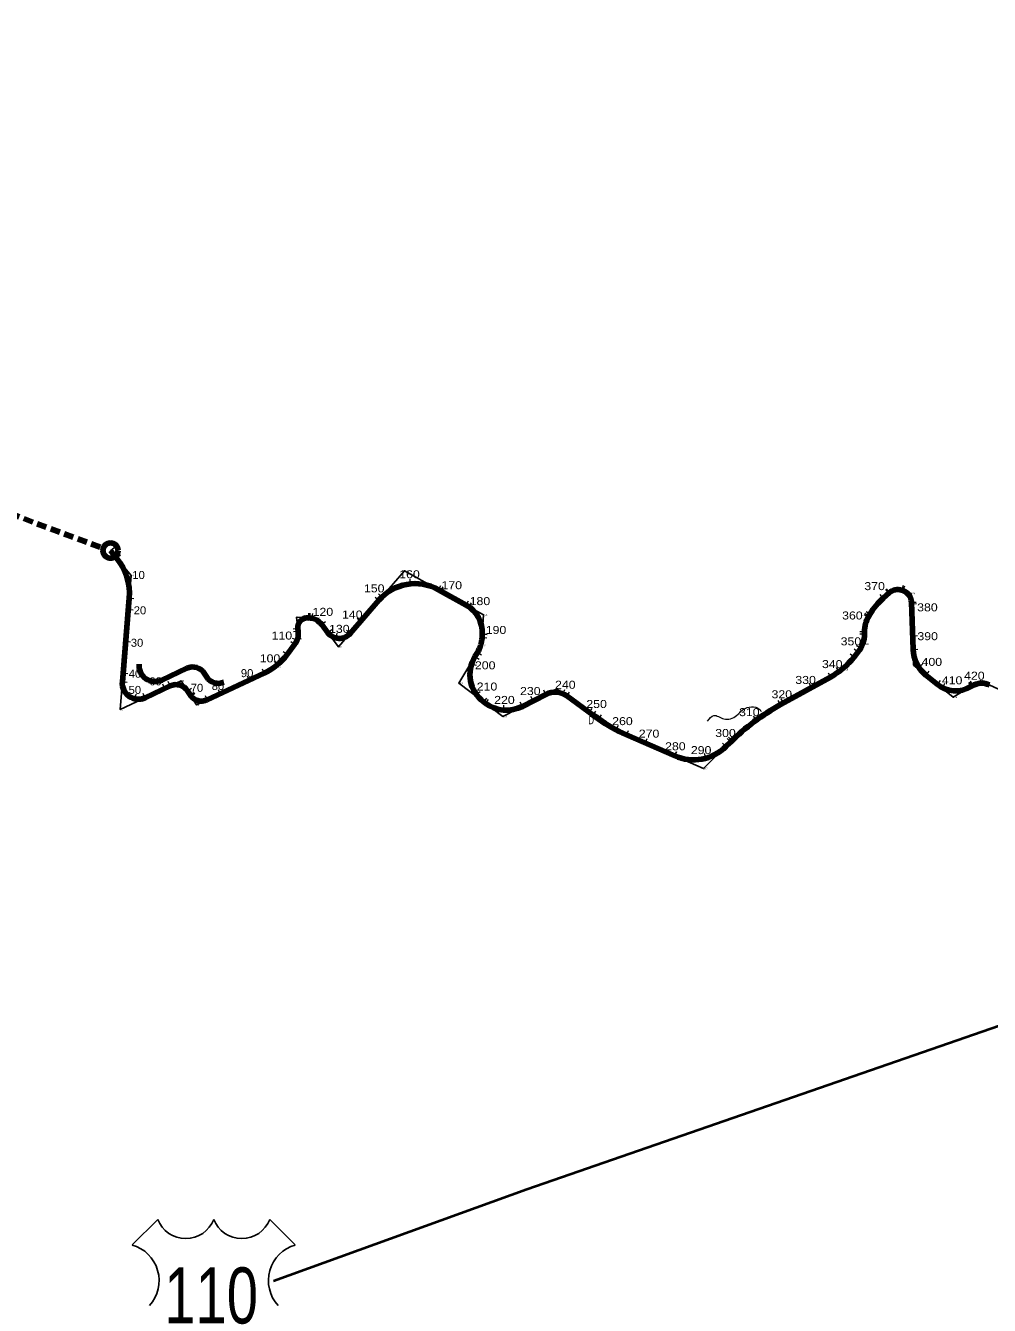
# Model space of a CAD drawing. Extents: x 553962 to 842807, y 8883888 to 9032388.
# Drawn here: x 591570 to 597590, y 8961821 to 8969814 of the extents above; entities that cross this region are included whole.
import ezdxf
from ezdxf.enums import TextEntityAlignment as Align

# ---------------------------------------------------------------- set-up
doc = ezdxf.new("R2010")
doc.units = 0
doc.header["$LTSCALE"] = 20
doc.linetypes.add('MEDIUM_DASHED', pattern=[4.5, 3, -1.5])
for name, color, linetype, lineweight in [('12', 7, 'Continuous', 25), ('14', 7, 'Continuous', 13), ('15', 7, 'Continuous', 90), ('26', 7, 'Continuous', 13), ('27', 7, 'Continuous', 13), ('48', 7, 'Continuous', 25), ('60', 7, 'Continuous', 25), ('9', 7, 'Continuous', 90)]:
    doc.layers.add(name, color=color, linetype=linetype, lineweight=lineweight)
doc.layers.add('13', color=7, linetype='Continuous')
doc.layers.add('61', color=7, linetype='Continuous')

msp = doc.modelspace()

# ---------------------------------------------------------------- linework, layer by layer
at = {"layer": '12', "lineweight": 40}
msp.add_lwpolyline([(593118.32, 8961975.46), (594700.75, 8962547.46), (600985.52, 8964722.42), (602091.61, 8965119.89), (602697.14, 8965318.89), (609861.02, 8967928.67)], dxfattribs=at)
at = {"layer": '14'}
for p, q in [((592100.12, 8966535.41), (592123.3, 8966554.46)), ((592138.38, 8966488.86), (592161.56, 8966507.91)), ((592203.51, 8966366.27), (592232.27, 8966374.81)), ((593969.03, 8966357.29), (593972.16, 8966327.46)), ((593753.69, 8966244.76), (593776.4, 8966225.15)), ((593773.46, 8966265.73), (593794.37, 8966244.22)), ((594149.38, 8966291.21), (594163.97, 8966317.42)), ((594163.58, 8966283.3), (594178.17, 8966309.52)), ((596927.13, 8966237.96), (596907.15, 8966260.34)), ((596927.13, 8966237.96), (596966.92, 8966273.47)), ((596962.82, 8966269.81), (596942.85, 8966292.2)), ((596966.92, 8966273.47), (596946.94, 8966295.85)), ((597051.8, 8966316.53), (597041.82, 8966288.24)), ((597041.82, 8966288.24), (597050.5, 8966285.18)), ((597060.49, 8966313.47), (597050.5, 8966285.18)), ((592211.1, 8966167.94), (592241, 8966165.49)), ((592216.84, 8966238.09), (592246.74, 8966235.64)), ((594322.59, 8966194.79), (594337.18, 8966221)), ((594337.9, 8966185.32), (594354.85, 8966210.07)), ((597103.83, 8966212.42), (597133.81, 8966213.43)), ((597103.83, 8966212.42), (597113.72, 8965917.79)), ((597104.14, 8966203.06), (597134.13, 8966204.06)), ((593336.38, 8966144.88), (593334.29, 8966114.96)), ((593345.48, 8966144.25), (593343.4, 8966114.32)), ((593361.44, 8966142.17), (593355.81, 8966112.71)), ((593443.72, 8966091.06), (593419.8, 8966072.95)), ((593640.11, 8966113.21), (593662.81, 8966093.61)), ((596833.3, 8966119.11), (596807.01, 8966133.57)), ((596837.45, 8966126.36), (596811.79, 8966141.89)), ((596837.45, 8966126.36), (596811.79, 8966141.89)), ((596819.93, 8966155.35), (596845.6, 8966139.81)), ((596837.45, 8966126.36), (596845.6, 8966139.81)), ((593270.53, 8966048.04), (593240.74, 8966044.51)), ((593272.56, 8966030.89), (593242.77, 8966027.36)), ((593481.76, 8966040.82), (593457.84, 8966022.71)), ((593514.35, 8966019), (593506.73, 8965989.99)), ((593575.01, 8966037.82), (593597.72, 8966018.22)), ((594452.31, 8966010.45), (594422.37, 8966012.31)), ((594422.45, 8966013.66), (594452.4, 8966012.01)), ((596810, 8966027.98), (596780, 8966027.98)), ((596780, 8966016.13), (596810, 8966016.13)), ((596810, 8966016.13), (596810, 8966027.98)), ((597110.85, 8966003.17), (597140.84, 8966004.18)), ((592194.8, 8965968.6), (592224.7, 8965966.16)), ((593250.17, 8965948.11), (593226.22, 8965966.17)), ((593265.77, 8965976.28), (593237.75, 8965987)), ((594451.01, 8965989.47), (594421.07, 8965991.33)), ((596787.06, 8965926.93), (596760.74, 8965941.32)), ((593122.28, 8965844.29), (593141.37, 8965821.15)), ((593202.87, 8965885.4), (593178.92, 8965903.46)), ((594376.43, 8965873.69), (594402.06, 8965858.1)), ((594392.31, 8965899.78), (594417.93, 8965884.18)), ((596744.69, 8965869.75), (596721.31, 8965888.55)), ((596744.69, 8965869.75), (596769.19, 8965900.23)), ((596769.19, 8965900.23), (596745.81, 8965919.03)), ((597113.72, 8965917.79), (597143.7, 8965918.8)), ((592178.5, 8965769.27), (592208.4, 8965766.82)), ((593047.74, 8965797.18), (593060.45, 8965770)), ((594355.56, 8965828.18), (594384.1, 8965818.94)), ((596582.31, 8965771.63), (596596.82, 8965745.37)), ((596652.08, 8965780.85), (596634.22, 8965804.96)), ((597147.19, 8965809.63), (597172.54, 8965825.67)), ((597211.83, 8965781.51), (597192.89, 8965758.24)), ((592174.07, 8965715.07), (592203.97, 8965712.63)), ((592439.77, 8965674.44), (592427.01, 8965701.6)), ((592473.48, 8965690.28), (592460.72, 8965717.44)), ((592953.52, 8965753.12), (592966.23, 8965725.94)), ((596285.55, 8965573.36), (596596.82, 8965745.37)), ((596479.29, 8965680.42), (596464.78, 8965706.68)), ((597192.89, 8965758.24), (597263.15, 8965701.07)), ((597282.09, 8965724.34), (597263.15, 8965701.07)), ((597310.43, 8965706.01), (597296.98, 8965679.19)), ((597459.9, 8965711.78), (597475.38, 8965686.09)), ((597467.18, 8965716.17), (597482.66, 8965690.47)), ((597487.18, 8965693.05), (597472.73, 8965719.34)), ((597475.3, 8965686.04), (597482.66, 8965690.47)), ((592254.25, 8965608.84), (592260.09, 8965638.26)), ((592316.26, 8965616.41), (592303.5, 8965643.57)), ((592581.21, 8965659.16), (592606.48, 8965675.34)), ((592596.86, 8965634.72), (592622.13, 8965650.89)), ((592603.55, 8965625.65), (592626.46, 8965645.02)), ((592691.75, 8965630.72), (592704.46, 8965603.54)), ((592772.35, 8965668.4), (592785.06, 8965641.23)), ((594384.74, 8965637.53), (594409.21, 8965654.89)), ((594449.1, 8965613.93), (594431.1, 8965589.93)), ((594459.22, 8965606.34), (594441.22, 8965582.34)), ((594740.24, 8965596.59), (594726.61, 8965623.31)), ((594819.94, 8965637.26), (594806.3, 8965663.98)), ((594926.85, 8965640.45), (594938.88, 8965667.93)), ((594949.95, 8965627.26), (594967.51, 8965651.58)), ((596304.24, 8965583.69), (596289.73, 8965609.95)), ((594555.16, 8965569.2), (594552.31, 8965539.33)), ((594673.23, 8965562.38), (594659.59, 8965589.1)), ((595090.48, 8965525.77), (595108.05, 8965550.09)), ((595114.31, 8965508.56), (595131.87, 8965532.88)), ((596285.55, 8965573.36), (596271.04, 8965599.62)), ((595165.33, 8965508.71), (595147.76, 8965484.39)), ((596135, 8965477.42), (596117.29, 8965501.63)), ((595271.55, 8965442.56), (595257.47, 8965416.07)), ((595322.97, 8965384.42), (595334.97, 8965411.91)), ((595961.24, 8965370.27), (595982.11, 8965348.73)), ((595439.58, 8965333.52), (595451.58, 8965361.01)), ((595923.69, 8965333.3), (595944.76, 8965311.95)), ((595951.61, 8965360.86), (595972.69, 8965339.51)), ((595622.87, 8965253.5), (595634.87, 8965281)), ((595625.03, 8965252.56), (595637.03, 8965280.06)), ((595818.39, 8965238.85), (595810.39, 8965267.76))]:
    msp.add_line(p, q, dxfattribs=at)
for centre, radius, start, end in [((597016.86, 8966217.52), 75, 70.55997, 131.75089), ((597023.88, 8966209.74), 80, 1.92196, 70.55996), ((597213.46, 8965917.16), 430, 131.75089, 148.81502), ((597000, 8966027.98), 190, 148.81502, 180), ((596625, 8966016.13), 185, 321.20777, 0), ((596354.98, 8966182.99), 500, 298.92642, 321.20777), ((597328.6, 8965925), 215, 181.92196, 230.8625), ((597379.92, 8965844.56), 185, 230.8625, 301.0622), ((597379.92, 8965844.56), 185, 243.36383, 301.03315), ((597541.99, 8965591.96), 115, 65.09523, 121.0622), ((596977.22, 8964321.76), 1430, 118.92642, 134.09739)]:
    msp.add_arc(centre, radius, start, end, dxfattribs=at)
msp.add_spline([(595830.1, 8965470.36), (595868.38, 8965505.89), (595932.18, 8965484.24), (596010.41, 8965504.78), (596052.02, 8965543.08), (596152.43, 8965545.85), (596165.19, 8965530.86)], degree=3, dxfattribs=at)
at = {"layer": '15', "linetype": 'MEDIUM_DASHED'}
msp.add_line((590039.76, 8967299.35), (592054.89, 8966550.12), dxfattribs=at)
at = {"layer": '15'}
for p, q in [((592100.12, 8966535.41), (592138.38, 8966488.86)), ((594149.38, 8966291.21), (594322.59, 8966194.79)), ((594149.38, 8966291.21), (594322.59, 8966194.79)), ((596927.13, 8966237.96), (596966.92, 8966273.47)), ((597041.82, 8966288.24), (597050.5, 8966285.18)), ((592216.84, 8966238.09), (592174.07, 8965715.07)), ((593597.72, 8966018.22), (593776.4, 8966225.15)), ((593597.72, 8966018.22), (593776.4, 8966225.15)), ((597103.83, 8966212.42), (597113.72, 8965917.79)), ((593334.29, 8966114.96), (593343.4, 8966114.32)), ((593334.29, 8966114.96), (593343.4, 8966114.32)), ((596837.45, 8966126.36), (596845.6, 8966139.81)), ((593272.56, 8966030.89), (593270.53, 8966048.04)), ((593272.56, 8966030.89), (593270.53, 8966048.04)), ((593419.8, 8966072.95), (593457.84, 8966022.71)), ((593419.8, 8966072.95), (593457.84, 8966022.71)), ((594422.37, 8966012.31), (594421.07, 8965991.33)), ((594422.37, 8966012.31), (594421.07, 8965991.33)), ((596810, 8966016.13), (596810, 8966027.98)), ((593202.87, 8965885.4), (593250.17, 8965948.11)), ((593202.87, 8965885.4), (593250.17, 8965948.11)), ((594392.31, 8965899.78), (594376.43, 8965873.69)), ((594392.31, 8965899.78), (594376.43, 8965873.69)), ((596744.69, 8965869.75), (596769.19, 8965900.23)), ((592420.47, 8965726.85), (592577.69, 8965800.71)), ((592685.42, 8965769.6), (592701.07, 8965745.16)), ((592704.46, 8965603.54), (593060.45, 8965770)), ((592316.26, 8965616.41), (592473.48, 8965690.28)), ((596285.55, 8965573.36), (596596.82, 8965745.37)), ((597192.89, 8965758.24), (597263.16, 8965701.06)), ((597475.3, 8965686.04), (597482.66, 8965690.47)), ((592581.21, 8965659.16), (592596.86, 8965634.72)), ((594673.23, 8965562.38), (594819.94, 8965637.26)), ((594673.23, 8965562.38), (594819.94, 8965637.26)), ((594949.95, 8965627.26), (595114.31, 8965508.56)), ((594949.95, 8965627.26), (595114.31, 8965508.56)), ((594431.1, 8965589.93), (594441.22, 8965582.34)), ((594431.1, 8965589.93), (594441.22, 8965582.34)), ((595114.31, 8965508.55), (595147.76, 8965484.39)), ((595114.31, 8965508.55), (595147.76, 8965484.39)), ((595322.97, 8965384.42), (595625.03, 8965252.56)), ((595322.97, 8965384.42), (595625.03, 8965252.56)), ((595944.76, 8965311.95), (595972.69, 8965339.51)), ((595944.76, 8965311.95), (595972.69, 8965339.51))]:
    msp.add_line(p, q, dxfattribs=at)
msp.add_circle((592100.12, 8966535.41), 47.56, dxfattribs=at)
for centre, radius, start, end in [((591868, 8966266.61), 350, 355.32527, 39.41953), ((594003.46, 8966029.09), 300, 60.89618, 139.19118), ((594003.46, 8966029.09), 300, 60.89618, 139.19118), ((597016.86, 8966217.52), 75, 70.55997, 131.75089), ((597023.88, 8966209.74), 80, 1.92196, 70.55996), ((594227.75, 8966024.41), 195, 356.44215, 60.89618), ((594227.75, 8966024.41), 195, 356.44215, 60.89618), ((597213.46, 8965917.16), 430, 131.75089, 148.81502), ((593330.11, 8966055.1), 60, 86.00909, 186.75908), ((593330.11, 8966055.1), 60, 86.00909, 186.75908), ((593336.09, 8966009.58), 105, 37.12798, 86.00909), ((593336.09, 8966009.58), 105, 37.12798, 86.00909), ((597000, 8966027.98), 190, 148.81502, 180), ((593158.36, 8966017.36), 115, 322.97327, 6.75908), ((593158.36, 8966017.36), 115, 322.97327, 6.75908), ((593529.6, 8966077.04), 90, 217.12799, 319.19119), ((593529.6, 8966077.04), 90, 217.12799, 319.19119), ((596625, 8966016.13), 185, 321.20777, 0), ((594221.45, 8966003.74), 200, 328.67904, 356.44215), ((594221.45, 8966003.74), 200, 328.67904, 356.44215), ((592899.5, 8966114.23), 380, 295.06001, 322.97327), ((592899.5, 8966114.23), 380, 295.06001, 322.97327), ((594560.1, 8965761.93), 215, 148.67904, 233.1301), ((594560.1, 8965761.93), 215, 148.67904, 233.1301), ((596354.98, 8966182.99), 500, 298.92642, 321.20777), ((597328.6, 8965925), 215, 181.92196, 230.8625), ((592377.95, 8965817.36), 100, 175.32527, 295.1649), ((592613.83, 8965723.78), 85, 32.61924, 115.1649), ((592273.74, 8965706.92), 100, 175.32527, 295.1649), ((592509.62, 8965613.34), 85, 32.61924, 115.1649), ((592772.66, 8965790.97), 85, 212.61924, 295.06002), ((597379.92, 8965844.56), 185, 230.86502, 301.03315), ((597541.99, 8965591.96), 115, 65.09523, 121.0622), ((592668.45, 8965680.54), 85, 212.61924, 295.06002), ((594876.76, 8965525.93), 125, 54.16336, 117.03912), ((594876.76, 8965525.93), 125, 54.16336, 117.03912), ((594573.22, 8965758.34), 220, 233.1301, 297.03912), ((594573.22, 8965758.34), 220, 233.1301, 297.03912), ((596977.22, 8964321.76), 1430, 118.92642, 134.62552), ((595701.03, 8966250.5), 945, 234.16361, 246.41769), ((595701.03, 8966250.5), 945, 234.16361, 246.41769), ((595741.05, 8965518.34), 290, 246.41768, 314.62552), ((595741.05, 8965518.34), 290, 246.41768, 314.62552)]:
    msp.add_arc(centre, radius, start, end, dxfattribs=at)
at = {"layer": '26'}
for p, q in [((592100.12, 8966535.41), (592138.38, 8966488.86)), ((594149.38, 8966291.21), (594322.59, 8966194.79)), ((596927.13, 8966237.96), (596966.92, 8966273.47)), ((597041.82, 8966288.24), (597050.5, 8966285.18)), ((592216.84, 8966238.09), (592174.07, 8965715.07)), ((593597.72, 8966018.22), (593776.4, 8966225.15)), ((597103.83, 8966212.42), (597113.72, 8965917.79)), ((593334.29, 8966114.96), (593343.4, 8966114.32)), ((596837.45, 8966126.36), (596845.6, 8966139.81)), ((593272.56, 8966030.89), (593270.53, 8966048.04)), ((593419.8, 8966072.95), (593457.84, 8966022.71)), ((594422.37, 8966012.31), (594421.07, 8965991.33)), ((596810, 8966016.13), (596810, 8966027.98)), ((593202.87, 8965885.4), (593250.17, 8965948.11)), ((594392.31, 8965899.78), (594376.43, 8965873.69)), ((596744.69, 8965869.75), (596769.19, 8965900.23)), ((592704.46, 8965603.54), (593060.45, 8965770)), ((592316.26, 8965616.41), (592473.48, 8965690.28)), ((596285.55, 8965573.36), (596596.82, 8965745.37)), ((597192.89, 8965758.24), (597263.16, 8965701.06)), ((597475.3, 8965686.04), (597482.66, 8965690.47)), ((592581.21, 8965659.16), (592596.86, 8965634.72)), ((594673.23, 8965562.38), (594819.94, 8965637.26)), ((594431.1, 8965589.93), (594441.22, 8965582.34)), ((595322.97, 8965384.42), (595625.03, 8965252.56)), ((595944.76, 8965311.95), (595972.69, 8965339.51))]:
    msp.add_line(p, q, dxfattribs=at)
msp.add_lwpolyline([(594949.95, 8965627.26), (595114.31, 8965508.56), (595147.76, 8965484.39)], dxfattribs=at)
for centre, radius, start, end in [((591868, 8966266.61), 350, 355.32527, 39.41953), ((594003.46, 8966029.09), 300, 60.89618, 139.19118), ((597016.86, 8966217.52), 75, 70.55997, 131.75089), ((597023.88, 8966209.74), 80, 1.92196, 70.55996), ((594227.75, 8966024.41), 195, 356.44215, 60.89618), ((597213.46, 8965917.16), 430, 131.75089, 148.81502), ((593330.11, 8966055.1), 60, 86.00909, 186.75908), ((593336.09, 8966009.58), 105, 37.12798, 86.00909), ((597000, 8966027.98), 190, 148.81502, 180), ((593158.36, 8966017.36), 115, 322.97327, 6.75908), ((593529.6, 8966077.04), 90, 217.12799, 319.19119), ((596625, 8966016.13), 185, 321.20777, 0), ((594221.45, 8966003.74), 200, 328.67904, 356.44215), ((592899.5, 8966114.23), 380, 295.06001, 322.97327), ((594560.1, 8965761.93), 215, 148.67904, 233.1301), ((596354.98, 8966182.99), 500, 298.92642, 321.20777), ((597328.6, 8965925), 215, 181.92196, 230.8625), ((592273.74, 8965706.92), 100, 175.32527, 295.1649), ((592509.62, 8965613.34), 85, 32.61924, 115.1649), ((597379.92, 8965844.56), 185, 230.86502, 301.03315), ((597541.99, 8965591.96), 115, 65.09523, 121.0622), ((592668.45, 8965680.54), 85, 212.61924, 295.06002), ((594876.76, 8965525.93), 125, 54.16336, 117.03912), ((594573.22, 8965758.34), 220, 233.1301, 297.03912), ((596977.22, 8964321.76), 1430, 118.92642, 134.62552), ((595701.03, 8966250.5), 945, 234.16361, 246.41769), ((595741.05, 8965518.34), 290, 246.41768, 314.62552)]:
    msp.add_arc(centre, radius, start, end, dxfattribs=at)
at = {"layer": '27'}
for p, q in [((592100.12, 8966535.41), (592138.38, 8966488.86)), ((594149.38, 8966291.21), (594322.59, 8966194.79)), ((596927.13, 8966237.96), (596966.92, 8966273.47)), ((597041.82, 8966288.24), (597050.5, 8966285.18)), ((592216.84, 8966238.09), (592174.07, 8965715.07)), ((593597.72, 8966018.22), (593776.4, 8966225.15)), ((597103.83, 8966212.42), (597113.72, 8965917.79)), ((593334.29, 8966114.96), (593343.4, 8966114.32)), ((596837.45, 8966126.36), (596845.6, 8966139.81)), ((593272.56, 8966030.89), (593270.53, 8966048.04)), ((593419.8, 8966072.95), (593457.84, 8966022.71)), ((594422.37, 8966012.31), (594421.07, 8965991.33)), ((596810, 8966016.13), (596810, 8966027.98)), ((593202.87, 8965885.4), (593250.17, 8965948.11)), ((594392.31, 8965899.78), (594376.43, 8965873.69)), ((596744.69, 8965869.75), (596769.19, 8965900.23)), ((592704.46, 8965603.54), (593060.45, 8965770)), ((592316.26, 8965616.41), (592473.48, 8965690.28)), ((596285.55, 8965573.36), (596596.82, 8965745.37)), ((597192.89, 8965758.24), (597263.16, 8965701.06)), ((597475.3, 8965686.04), (597482.66, 8965690.47)), ((592581.21, 8965659.16), (592596.86, 8965634.72)), ((594673.23, 8965562.38), (594819.94, 8965637.26)), ((594431.1, 8965589.93), (594441.22, 8965582.34)), ((595322.97, 8965384.42), (595625.03, 8965252.56)), ((595944.76, 8965311.95), (595972.69, 8965339.51))]:
    msp.add_line(p, q, dxfattribs=at)
msp.add_lwpolyline([(594949.95, 8965627.26), (595114.31, 8965508.56), (595147.76, 8965484.39)], dxfattribs=at)
for centre, radius, start, end in [((591868, 8966266.61), 350, 355.32527, 39.41953), ((594003.46, 8966029.09), 300, 60.89618, 139.19118), ((597016.86, 8966217.52), 75, 70.55997, 131.75089), ((597023.88, 8966209.74), 80, 1.92196, 70.55996), ((594227.75, 8966024.41), 195, 356.44215, 60.89618), ((597213.46, 8965917.16), 430, 131.75089, 148.81502), ((593330.11, 8966055.1), 60, 86.00909, 186.75908), ((593336.09, 8966009.58), 105, 37.12798, 86.00909), ((597000, 8966027.98), 190, 148.81502, 180), ((593158.36, 8966017.36), 115, 322.97327, 6.75908), ((593529.6, 8966077.04), 90, 217.12799, 319.19119), ((596625, 8966016.13), 185, 321.20777, 0), ((594221.45, 8966003.74), 200, 328.67904, 356.44215), ((592899.5, 8966114.23), 380, 295.06001, 322.97327), ((594560.1, 8965761.93), 215, 148.67904, 233.1301), ((596354.98, 8966182.99), 500, 298.92642, 321.20777), ((597328.6, 8965925), 215, 181.92196, 230.8625), ((592273.74, 8965706.92), 100, 175.32527, 295.1649), ((592509.62, 8965613.34), 85, 32.61924, 115.1649), ((597379.92, 8965844.56), 185, 230.86502, 301.03315), ((597541.99, 8965591.96), 115, 65.09523, 121.0622), ((592668.45, 8965680.54), 85, 212.61924, 295.06002), ((594876.76, 8965525.93), 125, 54.16336, 117.03912), ((594573.22, 8965758.34), 220, 233.1301, 297.03912), ((596977.22, 8964321.76), 1430, 118.92642, 134.62552), ((595701.03, 8966250.5), 945, 234.16361, 246.41769), ((595741.05, 8965518.34), 290, 246.41768, 314.62552)]:
    msp.add_arc(centre, radius, start, end, dxfattribs=at)
at = {"layer": '48'}
for p, q in [((592235.21, 8962198.42), (592395.14, 8962358.32)), ((593094.46, 8962358.32), (593254.41, 8962198.42))]:
    msp.add_line(p, q, dxfattribs=at)
for centre, radius, start, end in [((592569.98, 8962425.29), 187.21, 200.95927, 339.04073), ((592919.63, 8962425.29), 187.21, 200.95927, 339.04073), ((592173.14, 8961976.56), 230.34, 317.5721, 74.36886), ((593316.47, 8961976.56), 230.34, 105.62774, 222.4279)]:
    msp.add_arc(centre, radius, start, end, dxfattribs=at)
at = {"layer": '60'}
msp.add_lwpolyline([(592100.12, 8966535.41), (592228.39, 8966379.36), (592160, 8965543), (592541, 8965722), (592637, 8965572), (593146, 8965810), (593278, 8965985), (593262, 8966120), (593391, 8966111), (593525, 8965934), (593936, 8966410), (594430, 8966135), (594418, 8965942), (594275, 8965707), (594551, 8965500), (594888, 8965672), (595114.31, 8965508.55), (595230, 8965425), (595805, 8965174), (596113, 8965478), (596683, 8965793), (596810, 8965951), (596810, 8966081), (596879, 8966195), (597000, 8966303), (597102, 8966267), (597117, 8965820), (597364, 8965619), (597535, 8965722), (597647, 8965670)], dxfattribs=at)
at = {"layer": '9'}
msp.add_spline([(592698.54, 8977198.44), (599903.54, 8973292.71), (608459.22, 8968138.19), (612674.79, 8965332.64), (616842.02, 8962096.37), (620004.97, 8958671.19), (621133.98, 8957974.71), (621473.43, 8956805.35), (621586.23, 8956597.47)], degree=3, dxfattribs=at)

# ---------------------------------------------------------------- texts
at = {"layer": '13'}
for s, width, p in [('10', 1.05, (592275.34, 8966358.08)), ('160', 1.15, (593967.89, 8966362.58)), ('150', 1.15, (593747.25, 8966274.56)), ('170', 1.15, (594231.82, 8966294.11)), ('370', 1.15, (596873.14, 8966288.5)), ('180', 1.15, (594407.77, 8966194.91)), ('20', 1.05, (592284.01, 8966137.38)), ('120', 1.15, (593426.78, 8966127.88)), ('380', 1.15, (597203.33, 8966155.96)), ('140', 1.15, (593610.4, 8966111.1)), ('360', 1.15, (596734.56, 8966105.04)), ('110', 1.15, (593170.53, 8965979.79)), ('130', 1.15, (593529.41, 8966021.69)), ('190', 1.15, (594508.31, 8966014.67)), ('390', 1.15, (597204.63, 8965975.76)), ('30', 1.05, (592265.81, 8965934.7)), ('350', 1.15, (596725.27, 8965943.56)), ('100', 1.15, (593096.53, 8965837.29)), ('200', 1.15, (594440.69, 8965793.86)), ('340', 1.15, (596608.66, 8965801.53)), ('400', 1.15, (597230.72, 8965815.14)), ('40', 1.05, (592252.9, 8965741.44)), ('90', 1.05, (592953.4, 8965745.09)), ('420', 1.15, (597496.4, 8965728.95)), ('50', 1.05, (592251.9, 8965640.22)), ('60', 1.05, (592380.86, 8965694.1)), ('70', 1.05, (592640.14, 8965653.52)), ('80', 1.05, (592771.16, 8965664.75)), ('210', 1.15, (594451.95, 8965661.37)), ('240', 1.15, (594941.24, 8965672.63)), ('330', 1.15, (596442.19, 8965702.61)), ('410', 1.15, (597357.41, 8965700.26)), ('220', 1.15, (594560.89, 8965577.74)), ('230', 1.15, (594722.42, 8965633.17)), ('320', 1.15, (596293.46, 8965612.99)), ('250', 1.15, (595136.58, 8965552.35)), ('310', 1.15, (596090.65, 8965501.4)), ('D', 0.65, (595102.96, 8965451.13)), ('260', 1.15, (595298.11, 8965445.23)), ('270', 1.15, (595464.33, 8965367.24)), ('300', 1.15, (595941.92, 8965371.2)), ('280', 1.15, (595628.68, 8965288.31)), ('290', 1.15, (595789.64, 8965264.37))]:
    msp.add_text(s, height=50, dxfattribs=dict(at, width=width)).set_placement(p, align=Align.CENTER)
at = {"layer": '48', "width": 0.75}
msp.add_text('110', height=350, dxfattribs=at).set_placement((592728.7, 8961708.4), align=Align.CENTER)
at = {"layer": '61'}
for s, p in [('V0', (592100.12, 8966530.41)), ('V11', (594430, 8966130)), ('V21', (596810, 8966076)), ('V6', (593278, 8965980))]:
    msp.add_text(s, height=10, dxfattribs=at).set_placement(p)
for s, width, p in [('V10', 1.1, (593936, 8966405)), ('V1', 0.9, (592228.39, 8966374.36)), ('V23', 1.05, (597000, 8966298)), ('V24', 1.05, (597102, 8966262)), ('V22', 1.05, (596879, 8966190)), ('V7', 0.95, (593262, 8966115)), ('V8', 0.95, (593391, 8966106)), ('V9', 0.95, (593525, 8965929)), ('V12', 1.05, (594418, 8965937)), ('V20', 1.1, (596810, 8965946)), ('V5', 0.95, (593146, 8965805)), ('V19', 1.05, (596683, 8965788)), ('V25', 1.05, (597117, 8965815)), ('V3', 0.95, (592541, 8965717)), ('V13', 1.05, (594275, 8965702)), ('V27', 1.05, (597535, 8965717)), ('V15', 1.05, (594888, 8965667)), ('V26', 1.05, (597364, 8965614)), ('V2', 0.95, (592160, 8965538)), ('V4', 0.95, (592637, 8965567)), ('V14', 1.05, (594551, 8965495)), ('V15A', 1.1, (595114.31, 8965503.55)), ('V18', 1.05, (596113, 8965473)), ('V16', 1.05, (595230, 8965420)), ('V17', 1.05, (595805, 8965169))]:
    msp.add_text(s, height=10, dxfattribs=dict(at, width=width)).set_placement(p)

doc.saveas('drawing.dxf')
